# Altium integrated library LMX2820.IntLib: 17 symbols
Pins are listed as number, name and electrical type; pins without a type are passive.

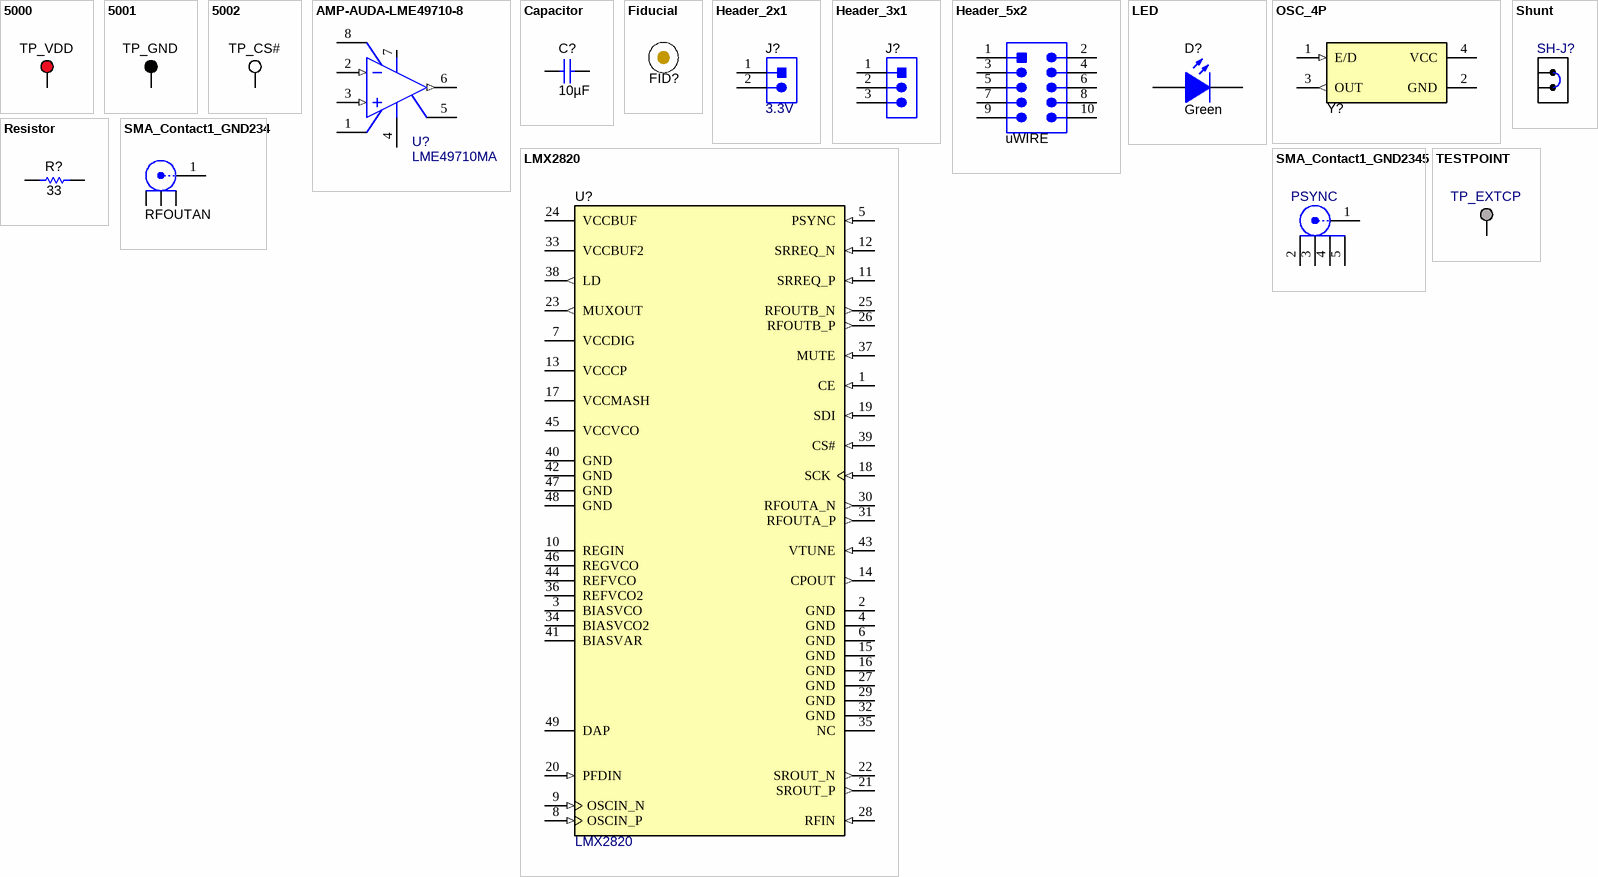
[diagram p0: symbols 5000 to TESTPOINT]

## 5000
designator TP?, comment TP_VDD
Test Point, Miniature, Red, TH; PartNumber: 5000; Manufacturer: Keystone; ContactFinish: Silver; Green_Lifecycle: Active; Green_REACh: Passed; CNHeader: FALSE; CT: TRUE
footprint Keystone5000 (For Keystone 500x miniature loop terminals)
pins: 1

## 5001
designator TP?, comment TP_GND
Test Point, Miniature, Black, TH; PartNumber: 5001; Manufacturer: Keystone; ContactFinish: Silver; Green_Lifecycle: Active; Green_REACh: Passed; CNHeader: FALSE; CT: TRUE
footprint Keystone5001 (For Keystone 500x miniature loop terminals)
pins: 1

## 5002
designator TP?, comment TP_CS#
Test Point, Miniature, White, TH; PartNumber: 5002; Manufacturer: Keystone; ContactFinish: Silver; Green_Lifecycle: Active; Green_REACh: Passed; CNHeader: FALSE; CT: TRUE
footprint Keystone5002 (For Keystone 500x miniature loop terminals)
pins: 1

## AMP-AUDA-LME49710-8
designator U?, comment LME49710MA
High Performance, High Fidelity Audio Operational Amplifier, 8-pin Narrow SOIC, Pb-Free; Manufacturer: Texas Instruments; PartNumber: LME49710MA/NOPB; CompType: IC; AEC Category: Q200; AEC Qualified: N; SizeAreaWB_mm2: 56.58; SizeArea_mm2: 30.38; SizeX_mm: 4.9; SizeY_mm: 6.2; SizeZ_mm: 1.75
footprint D0008A_N (SOIC, 8-Leads, Body 4.9x3.9mm, Pitch 1.27mm, IPC Medium Density)
footprint D0008A_M (SOIC, 8-Leads, Body 4.9x3.9mm, Pitch 1.27mm, IPC Low Density)
footprint D0008A_L (SOIC, 8-Leads, Body 4.9x3.9mm, Pitch 1.27mm, IPC High Density)
pins: 1 NC, 2 -IN (in), 3 +IN (in), 4 V- (power), 5 NC, 6 OUTPUT (out), 7 V+ (power), 8 NC

## Capacitor
designator C?, comment ValueDisplayed: 10µF  (hidden comment: GRM188R61A106KAALD)
CAP, CERM, 10 µF, 10 V,+/- 10%, X5R, 0603; Manufacturer: MuRata; SizeY_mm: 0.8; CompType: Capacitor; SizeAreaWB_mm2: 4.68; SizeX_mm: 1.6; SizeArea_mm2: 1.28; VDC_V: 10V; AEC Qualified: N; Cap_Case: 0603; Value: 10uF; U/M: EA; SizeZ_mm: 1; TaMax_C: 85°C; AEC Category: Q200; TaMin_C: -55°C
footprint 0603 (0603 from SM-752 data)
footprint 0603M (0603 from SM-752 data)
footprint 0603L (0603 from SM-752 data)
footprint 0603_HV (Ernesto recommended land pattern.  26 mil between pads.)
footprint 0603S
pins: 1, 2

## Fiducial
designator FID?  (value not drawn)
Fiducial mark.  There is nothing to buy or mount.
footprint Fiducial10-30
footprint Fiducial15-30
footprint Fiducial10-20
footprint Fiducial20-40
footprint Fiducial6.4-20

## Header_2x1
designator J?, comment 3.3V
Header, 100mil, 2x1, Gold, TH; Manufacturer: Samtec; PartNumber: TSW-102-07-G-S; Current_A: 6.3A; Green_Lifecycle: Active; Pitch_mm: 2.54; Cert_CSA: Y; Cert_VDE: N; Green_REACh: Passed; Row_Count: 1; Gender: Male; Voltage_V: 550V
footprint TSW-102-07-G-S (Samtec 100mil, 1x2, 230 mil above insulator)
pins: 1, 2
1 alternate drawing of the same symbol

## Header_3x1
designator J?, comment TSW-103-07-G-S  (value not drawn)
Header, 100mil, 3x1, Gold, TH; Manufacturer: Samtec; Pitch_mm: 2.54; Cert_VDE: N; Gender: Male; Cert_CSA: Y; Voltage_V: 550V; Green_REACh: Passed; Current_A: 6.3A; Green_Lifecycle: Active; Row_Count: 1
footprint TSW-103-07-G-S (Samtec 100mil, 1x3, 230 mil above insulator)
pins: 1, 2, 3
3 alternate drawings of the same symbol

## Header_5x2
designator J?, comment uWIRE
Header (shrouded), 100mil, 5x2, Gold, SMT; Manufacturer: FCI; PartNumber: 52601-S10-8LF; Green_Lifecycle: Active; Green_REACh: Passed
footprint FCI_52601-S10-8LF (FCI Electronics)
pins: 1, 2, 3, 4, 5, 6, 7, 8, 9, 10
1 alternate drawing of the same symbol

## LED
designator D?, comment value Green  (hidden comment: LTST-C190GKT)
LED, Green, SMD; Manufacturer: Lite-On; Power_TotalModule: 100mW; Value2: 2.1V; Io_A: 20mA; Value1: 0.1W
footprint LED_LTST-C190 (Lite-On)
pins: 1 A, 2 K

## LMX2820
designator U?
22-GHz Wideband PLLatinum™ RF Synthesizer With Phase Synchronization and JESD204B Support, RTC0048A (PVQFN-64); Manufacturer: Texas Instruments; PartNumber: LMX2820RTCR; AEC Qualified: N; SizeZ_mm: 0.9; SizeAreaWB_mm2: 81; AEC Category: Q200; CompType: IC; SizeArea_mm2: 49; SizeX_mm: 7
footprint RTC0048A (PVQFN, 64-Leads, Body 7x7mm, Pitch 0.5mm)
pins: 1 CE (in), 2 GND (power), 3 BIASVCO, 4 GND (power), 5 PSYNC (in), 6 GND (power), 7 VCCDIG (power), 8 OSCIN_P (in), 9 OSCIN_N (in), 10 REGIN, 11 SRREQ_P (in), 12 SRREQ_N (in), 13 VCCCP (power), 14 CPOUT (out), 15 GND (power), 16 GND (power), 17 VCCMASH (power), 18 SCK (in), 19 SDI (in), 20 PFDIN (in), 21 SROUT_P (out), 22 SROUT_N (out), 23 MUXOUT (out), 24 VCCBUF (power), 25 RFOUTB_N (out), 26 RFOUTB_P (out), 27 GND (power), 28 RFIN (in), 29 GND (power), 30 RFOUTA_N (out), 31 RFOUTA_P (out), 32 GND (power), 33 VCCBUF2 (power), 34 BIASVCO2, 35 NC, 36 REFVCO2, 37 MUTE (in), 38 LD (out), 39 CS# (in), 40 GND (power), 41 BIASVAR, 42 GND (power), 43 VTUNE (in), 44 REFVCO, 45 VCCVCO (power), 46 REGVCO, 47 GND (power), 48 GND (power), 49 DAP (power)

## OSC_4P
designator Y?, comment CWX813-100.0M  (value not drawn)
OSC 100.0000 MHz 3.3V +-25PPM SMD; Manufacturer: Connor-Winfield; TaMax_C: 70°C; TaMin_C: -20°C; CompType: Crystal; Frequency Stability: +/-25ppm; Frequency_Fixed: 100MHz
footprint OSC_CWX (CONNOR WINFIELD)
pins: 1 E/D (in), 2 GND (power), 3 OUT (out), 4 VCC (power)

## Resistor
designator R?, comment ValueDisplayed: 33  (hidden comment: CRCW060333R0JNEA)
RES, 33, 5%, 0.1 W, AEC-Q200 Grade 0, 0603; Manufacturer: Vishay-Dale; Power_W: 100mW; TempCo: 200 ppm/C; Value_Code: 33R0; Value: 33; EIA_Code: E24; SizeX_mm: 1.6; SizeY_mm: 0.8; SizeZ_mm: 1; Value2: 0.1W; SizeArea_mm2: 1.28; CompType: Resistor; AEC Qualified: Y; VDC_V: 75V; AEC Category: Q200; AEC Grade: 0
footprint 0603 (0603 from SM-752 data)
footprint 0603_HV (Ernesto recommended land pattern.  26 mil between pads.)
footprint 0603L (0603 from SM-752 data)
footprint 0603S
footprint 0603M (0603 from SM-752 data)
pins: 1, 2

## Shunt
designator SH-J?, comment SNT-100-BK-G  (value not drawn)
Shunt, 100mil, Gold plated, Black; Alternate PartNumber: 969102-0000-DA; Manufacturer: Samtec; Alternate Manufacturer: 3M; Value: 1x2; Note: You can "mate" this to a header by matching the designator.  i.e. use SH-J3 for header J3
footprint SNT-100-BK-G (Samtec STEP model)

## SMA_Contact1_GND234
designator J?, comment RFOUTAN
JACK, SMA, 50 Ohm, Gold, Edge Mount; PartNumber: 142-0771-831; Manufacturer: Cinch Connectivity; Voltage_V: 170V; Gender: Female
footprint Johnson_142-0771-831 (JACK, SMA, 50 Ohm, Gold, Edge Mount)
pins: 1, 2, 3, 4

## SMA_Contact1_GND2345
designator J?, comment PSYNC
CONN SMA JACK STR EDGE MNT; Manufacturer: RF Solutions Ltd.; PartNumber: CON-SMA-EDGE-S; ContactFinish: Gold; Shrouded: true
footprint FP-CON-SMA-EDGE-S_CONN_JACK-MFG
footprint FP-SMA-EDGE-S-CUSTOM
pins: 1, 2, 3, 4, 5

## TESTPOINT
designator TP?, comment TP_EXTCP  (no BOM)
TEST POINT.  No entry in BOM.
footprint TESTPOINT
footprint TP_VIA_018RND008
footprint TP_VIA_060RND040
footprint TP_25MIL-SMT
footprint TP_50MIL-25MILHOLE
footprint TP_60MIL-SMT
footprint TP_VIA_024RND014
footprint TP_50MIL-SMT
footprint TP_60MIL-SMT-155
pins: 1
